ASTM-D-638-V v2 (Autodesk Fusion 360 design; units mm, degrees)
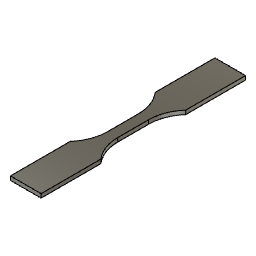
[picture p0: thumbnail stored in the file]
sketch "Sketch1" plane through (0, 0, 0) normal (0, 0, 1) x axis (1, 0, 0)
  line L1 (0, 31.75) -> (0, 0)
  line L2 (-1.59, 0) -> (0, 0)
  line L3 (-1.59, 4.765) -> (-1.59, 0)
  line L4 (-4.765, 31.75) -> (0, 31.75)
  line L5 (-4.765, 13.1653) -> (-4.765, 31.75)
  arc A1 centre (-14.29, 4.765) radius 12.7 clockwise from (-4.765, 13.1653) to (-1.59, 4.765)
  point P1 (0, 0)
  point P2 (0, 0)
  point P4 (0, 0)
  point P6 (-1.59, 4.765)
  point P3 (0, 31.75)
  coincident P1 P2
  vertical L1
  coincident P1 P4
  perpendicular L1 L2
  perpendicular L2 L3
  perpendicular L1 L4
  perpendicular L4 L5
  tangent L3 A1
  dimension "d1" distance P1 L3 = 1.59 (= "( 3.18 / 2 ) * 1 mm")
  dimension "d2" distance P1 P6 = 4.765 (= "( 9.53 / 2 ) * 1 mm")
  dimension "d3" radius A1 = 12.7
  dimension "d4" distance P3 L5 = 4.765 (= "( 9.53 / 2 ) * 1 mm")
  dimension "d5" distance P1 L4 = 31.75 (= "( 63.5 / 2 ) * 1 mm")
extrude "Extrude1" new body sketch "Sketch1" along normal blind 1.2 (= "( 0.2 * 6 ) * 1 mm") bodies "ASTM-D-638-V"
mirror "Mirror1"
combine "Combine1"
mirror "Mirror2"
combine "Combine2"
named bodies: "ASTM-D-638-V"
